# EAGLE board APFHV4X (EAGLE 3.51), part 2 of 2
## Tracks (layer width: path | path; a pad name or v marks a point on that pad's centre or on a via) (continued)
N$22  (via drill 0.05 pad 0.2) (continued)
  Bottom 0.1: v78.55,13.2 v83.92,18.58
N$23  (via drill 0.05 pad 0.2)
  Top 0.2: 85,17.27 85.6,17.27
  Top 0.4: 77.95,11.8 v78.35,11.8
  Top 0.5: v84.72,17.27 85,17.27
  Bottom 0.2: v78.35,11.8 79.25,11.8
  Bottom 0.5: 84.3,16.85 v84.72,17.27
  Bottom 0.8: 79.25,11.8 79.35,11.9
  Bottom 1: 79.35,11.9 84.3,16.85
N$24
  Top 0.4: 77.95,12.3 78.4,12.3 79.32,13.23 79.32,13.43
  Top 0.5: 85.6,17.93 83.82,17.93 83.15,17.25
  Top 1: 79.32,13.43 83.15,17.25
N$25  (via drill 0.05 pad 0.2)
  Top 0.3: v84.75,15.98 85.6,15.98
  Top 0.4: 77.95,10.8 v78.35,10.8
  Bottom 0.2: v78.35,10.8 79.85,10.8
  Bottom 0.3: 84.35,15.3 84.75,15.7 v84.75,15.98
  Bottom 1: 79.85,10.8 84.35,15.3
N$26
  Top 0.1: 85.6,4.28 84.7,4.28 83.7,3.28 77.95,3.28
N$27
  Top 0.1: 85.6,3.63 84.7,3.63 84.05,2.98 77.95,2.98
N$28
  Top 0.1: 85.6,2.98 84.7,2.98 84.4,2.68 JP2_.2
N$29
  Top 0.1: JP2_.6 84.38,2.08 84.78,1.68 85.6,1.68
N$30
  Top 0.1: JP2_.8 84.12,1.78 84.85,1.05 85.22,1.05 85.25,1.03 85.6,1.03
N$32
  Top 0.1: 85.6,2.33 84.67,2.33 84.62,2.38 JP2_.4
N$33
  Top 0.1: JP2_.0 83.75,1.48 84.85,0.38 CN_T.
N$38
  Top 0.075: 13.4,0.8 13.4,0.4
N$39
  Top 0.075: 13.4,1.4 13.4,1
N$40
  Top 0.075: 13.9,0.9 13.5,0.9
N$41
  Top 0.075: 12.9,0.9 13.3,0.9
N$42
  Top 0.075: 13.9,18.7 13.5,18.7
N$43
  Top 0.075: 13.4,18.2 13.4,18.6
N$44
  Top 0.075: 12.9,18.7 13.3,18.7
N$45
  Top 0.075: 13.4,19.2 13.4,18.8
N$46
  Top 0.075: 73.2,18.2 73.2,18.6
N$47
  Top 0.075: 73.7,18.7 73.3,18.7
N$48
  Top 0.075: 72.7,18.7 73.1,18.7
N$49
  Top 0.075: 73.2,19.2 73.2,18.8
N$50
  Top 0.075: 73.2,1.23 73.2,1
N$51
  Top 0.075: 73.2,0.4 73.2,0.8
N$52
  Top 0.075: 73.7,0.9 73.3,0.9
N$53
  Top 0.075: 72.7,0.9 73.1,0.9
NTC
  Top 0.1: 63.35,7.8 63.35,7.15 63.72,6.78 65.45,6.78 65.72,6.5 TR1.
  Top 0.3: 63.35,7.8 63.35,8.62
NTC_RET
  Top 0.1: 61.85,7.8 61.85,7.35 63.67,5.53 64.17,5.53
  Top 0.3: 61.85,7.8 61.85,8.62
RSIB  (via drill 0.05 pad 0.2)
  Top 0.1: 73.3,10.3 72.55,10.3 72.38,10.12 v72.38,9.08 | v35.32,10.5 35.32,6.75 35.55,6.53 U1.B
  Top 0.3: 60.35,7.8 v60.35,8.88 v60.35,10.78
  Bottom 0.1: v60.35,8.88 60.4,8.83 72.12,8.83 v72.38,9.08 | v35.32,10.5 37.45,10.5 38.05,9.9 38.67,9.9 39.02,9.55 40.17,9.55 40.92,10.3 46.52,10.3 47,10.78 v60.35,10.78
STRN  (via drill 0.05 pad 0.2)
  Top 0.075: 15.07,16.93 15.57,17.43 FE-7.2 | 22.67,16.93 23.17,17.43 FE-6.2 | 30.27,16.93 30.77,17.43 FE-5.2 | 37.88,16.93 38.38,17.43 FE-4.2 | 45.47,16.93 45.97,17.43 FE-3.2 | 53.07,16.93 53.57,17.43 FE-2.2 | 60.67,16.93 61.17,17.43 FE-1.2 | 68.28,16.93 68.78,17.43 FE-0.2 | 18.32,2.68 17.82,2.18 FE-8.2 | 25.92,2.68 25.42,2.18 FE-9.2 | 33.52,2.68 33.02,2.18 FE-10.2 | 41.12,2.68 40.62,2.18 FE-11.2 | 56.32,2.68 55.82,2.18 FE-13.2 | 63.92,2.68 63.42,2.18 FE-14.2 | 71.53,2.68 71.03,2.18 FE-15.2 | 48.72,2.68 48.22,2.18 FE-12.2
  Top 0.1: v15.07,15.7 15.07,16.93 | v22.67,15.7 22.67,16.93 | v30.25,15.7 30.27,15.7 30.27,16.93 | v37.88,15.7 37.88,16.93 | v45.47,15.7 45.47,16.93 | v53.07,15.7 53.07,16.93 | v60.67,15.7 60.67,16.93 | v68.28,15.7 68.28,16.93 | 18.32,2.68 18.32,3.35 v18.87,3.9 | v25.92,3.9 25.92,2.68 | v33.52,3.9 33.52,2.68 | v41.12,3.9 41.12,2.68 | v56.32,3.9 56.32,2.68 | v63.92,3.9 63.92,2.68 | 71.53,2.68 v71.53,3.9 71.9,3.9 72.82,2.98 73.3,2.98 | v48.72,3.9 48.72,2.68 | U1.ON 29.02,7.88 v29.02,7.93 29.02,9.6 28.8,9.83 v28.8,15.7 | v30.37,3.85 30.05,4.18 v30.05,7.93 | v30.37,3.85 30.32,3.8 | 29.2,3.38 29.9,3.38 v30.37,3.85
  Bottom 0.1: v71.53,3.9 v63.92,3.9 v56.32,3.9 v48.72,3.9 v41.12,3.9 41.12,3.88 41.05,3.8 34,3.8 33.9,3.9 v33.52,3.9 30.37,3.9 | v18.87,3.9 v25.92,3.9 26.3,3.9 26.4,3.8 30.12,3.8 30.22,3.9 30.37,3.9 | v15.07,15.7 v22.67,15.7 v28.8,15.7 v30.25,15.7 v37.88,15.7 v45.47,15.7 v53.07,15.7 v60.67,15.7 v68.28,15.7 | v30.05,7.93 v29.02,7.93 | 30.37,3.9 v30.37,3.85
STRP  (via drill 0.05 pad 0.2)
  Top 0.075: 14.82,17.02 15.42,17.62 FE-7.3 | 22.42,17.02 23.02,17.62 FE-6.3 | 30.05,17.05 30.62,17.62 FE-5.3 | 37.62,17.02 38.22,17.62 FE-4.3 | 52.82,17.02 53.42,17.62 FE-2.3 | 60.42,17.02 61.02,17.62 FE-1.3 | 68.03,17.02 68.62,17.62 FE-0.3 | 18.55,2.55 17.97,1.98 FE-8.3 | 26.17,2.58 25.57,1.98 FE-9.3 | 33.75,2.55 33.17,1.98 FE-10.3 | 41.38,2.58 40.77,1.98 FE-11.3 | 56.55,2.55 55.97,1.98 FE-13.3 | 64.15,2.55 63.57,1.98 FE-14.3 | 71.75,2.55 71.17,1.98 FE-15.3 | 48.95,2.55 48.38,1.98 FE-12.3 | FE-3.3 45.82,17.6 45.22,17
  Top 0.1: v14.82,15.95 14.82,17.02 | v22.42,15.95 22.42,17.02 | v37.62,15.95 37.62,17.02 | v45.22,15.95 45.22,17 | v52.82,15.95 52.82,17.02 | v60.42,15.95 60.42,17.02 | v68.03,15.95 68.03,17.02 | 18.55,2.55 18.55,2.98 v19.22,3.65 | 26.17,2.58 v26.17,3.65 26.87,3.65 | v41.38,3.65 41.38,2.58 | 56.55,2.55 56.57,2.58 v56.57,3.65 | 64.15,2.55 64.17,2.58 v64.17,3.65 | 71.75,2.55 71.78,2.58 71.78,3.13 | v71.78,3.65 71.78,3.13 | JP2_.1 72.72,2.68 72.28,3.13 71.78,3.13 | 48.95,2.55 48.97,2.58 v48.97,3.65 | v27.95,7.73 U1.OP | v26.92,15.95 v26.92,7.73 26.87,7.68 26.87,3.65 | R13. 27.15,3.38 26.87,3.65 | 30.05,17.05 30.02,17.02 v30.02,15.95 | v33.77,3.65 33.77,3.6 33.77,2.58 33.75,2.55
  Bottom 0.1: v71.78,3.65 v64.17,3.65 v56.57,3.65 v48.97,3.65 v41.38,3.65 41.32,3.6 33.82,3.6 v33.77,3.65 33.77,3.6 26.22,3.6 v26.17,3.65 v19.22,3.65 | v14.82,15.95 v22.42,15.95 v26.92,15.95 v30.02,15.95 v37.62,15.95 v45.22,15.95 v52.82,15.95 v60.42,15.95 v68.03,15.95 | v26.92,7.73 v27.95,7.73
SYNCN  (via drill 0.05 pad 0.2)
  Top 0.075: 16.57,16.75 16.47,16.85 16.47,18.05 | 24.17,16.75 24.07,16.85 24.07,18.05 | 31.77,16.75 31.67,16.85 31.67,18.05 | 39.38,16.75 39.27,16.85 39.27,18.05 | 46.97,16.75 46.88,16.85 46.88,18.05 | 54.57,16.75 54.47,16.85 54.47,18.05 | 62.17,16.75 62.07,16.85 62.07,18.05 | 69.78,16.75 69.67,16.85 69.67,18.05 | 16.82,2.85 16.92,2.75 16.92,1.55 | 24.42,2.85 24.52,2.75 24.52,1.55 | 32.02,2.85 32.12,2.75 32.12,1.55 | 39.62,2.85 39.72,2.75 39.72,1.55 | 62.42,2.85 62.52,2.75 62.52,1.55 | 47.22,2.85 47.32,2.75 47.32,1.55 | 54.82,2.85 54.92,2.75 54.92,1.55 | 70.03,2.85 70.12,2.75 70.12,1.55
  Top 0.1: v16.57,14.2 16.57,16.75 | v24.17,14.2 24.17,16.75 | v31.77,14.2 31.77,16.75 | v39.38,14.2 39.38,16.75 | v46.97,14.2 46.97,16.75 | v54.57,14.2 54.57,16.75 | v62.17,14.2 62.17,16.75 | v69.78,14.2 69.78,16.75 | v16.82,4.28 16.82,2.85 | v24.42,5.4 24.42,2.85 | v39.62,5.4 39.62,2.85 | v54.82,5.4 54.82,2.85 | v62.42,5.4 62.42,2.85 | 70.03,2.85 v70.03,5.4 71.95,5.4 72.57,4.78 73.3,4.78 | v47.22,5.4 47.22,2.85 | v32.02,5.4 32.02,2.85 | v28.65,6.68 U1.CN | v29.47,5.4 v29.47,6.68 | v29.3,14.2 29.3,9.95 29.52,9.73 v29.52,8.98 29.8,8.7 v29.8,7.35 | 25.47,9.62 25.47,9.12 v25.62,8.98
  Bottom 0.075: 27.02,5 26.62,5.4
  Bottom 0.1: v16.57,14.2 v24.17,14.2 v29.3,14.2 v31.77,14.2 v39.38,14.2 v46.97,14.2 v54.57,14.2 v62.17,14.2 v69.78,14.2 | v70.03,5.4 v62.42,5.4 v54.82,5.4 v47.22,5.4 v39.62,5.4 39.62,5.38 39.25,5 34.62,5 34.22,5.4 v32.02,5.4 v29.47,5.4 29.32,5.4 28.92,5 27.02,5 | 26.62,5.4 v24.42,5.4 17.05,5.4 16.82,5.18 v16.82,4.28 | v29.47,6.68 v28.65,6.68 | v29.52,8.98 v25.62,8.98 | v29.47,6.68 29.47,6.65 | v29.8,7.35 29.47,7.03 v29.47,6.68
SYNCP  (via drill 0.05 pad 0.2)
  Top 0.075: 16.32,16.45 16.32,18.05 | 23.92,16.45 23.92,18.05 | 31.52,16.45 31.52,18.05 | 39.12,16.45 39.12,18.05 | 46.72,16.45 46.72,18.05 | 54.32,16.45 54.32,18.05 | 61.92,16.45 61.92,18.05 | 69.53,16.45 69.53,18.05 | 17.07,3.15 17.07,1.55 | 24.67,3.15 24.67,1.55 | 32.27,3.15 32.27,1.55 | 39.88,3.15 39.88,1.55 | 47.47,3.15 47.47,1.55 | 55.07,3.15 55.07,1.55 | 62.67,3.15 62.67,1.55 | 70.28,3.15 70.28,1.55 | 26.62,6.5 v26.62,6.53 | v26.62,14.45 26.62,14.48
  Top 0.1: v16.32,14.45 16.32,16.45 | v23.92,14.45 23.92,16.45 | v31.52,14.45 31.52,16.45 | v39.12,14.45 39.12,16.45 | v46.72,14.45 46.72,16.45 | v54.32,14.45 54.32,16.45 | v61.92,14.45 61.92,16.45 | v69.53,14.45 69.53,16.45 | v17.07,4.08 17.07,3.15 | v24.67,5.15 24.67,3.15 | v32.27,5.15 32.27,3.15 | v39.88,5.15 39.88,3.15 | v55.07,5.15 55.07,3.15 | v62.67,5.15 62.67,3.15 | v70.28,5.15 70.28,3.15 | v72.95,4.48 JP2_. | v47.47,5.15 47.47,3.15 | v27.95,6.53 U1.CP | v26.62,6.53 26.62,10.35 | 26.62,10.35 v26.62,14.45 | R10. 24.37,10.2 v24.52,10.35 | 26.62,10.35 v26.67,10.35 | 26.62,6.5 26.62,5.38 v26.4,5.15
  Bottom 0.1: v16.32,14.45 v23.92,14.45 v26.62,14.45 v31.52,14.45 v39.12,14.45 v46.72,14.45 v54.32,14.45 v61.92,14.45 v69.53,14.45 | v17.07,4.08 17.07,4.83 17.4,5.15 v24.67,5.15 v26.4,5.15 26.57,5.15 26.92,4.8 29.12,4.8 29.47,5.15 v32.27,5.15 34.15,5.15 34.5,4.8 39.55,4.8 39.88,5.13 v39.88,5.15 v47.47,5.15 v55.07,5.15 v62.67,5.15 v70.28,5.15 70.88,5.15 71.55,4.48 v72.95,4.48 | v26.62,6.53 v27.95,6.53 | v26.67,10.35 v24.52,10.35
TS1
  Top 1: 1.5,18.27 1.5,8.28
TS2
  Top 0.1: 2.62,12.23 2.62,2.23
TS3  (via drill 0.05 pad 0.2)
  Top 0.1: v5.9,12.68 5.9,13.15 | v5.9,3.75 5.9,3.15
  Bottom 0.1: v5.9,12.68 v5.9,3.75
TS-VIA1  (via drill 0.05 pad 0.2)
  Top 0.1: v3.6,16.2 3.6,16 3.9,16 v3.9,16.2 | v3.6,16.5 3.6,16.7 | v3.9,16.5 3.9,16.7 4.2,16.7 v4.2,16.5 | v4.2,16.2 4.2,16 4.5,16 v4.5,16.2 | v4.5,16.5 4.5,16.7 4.8,16.7 v4.8,16.5 | v4.8,16.2 4.8,16 5.1,16 v5.1,16.2 | v5.1,16.5 5.1,16.7 5.4,16.7 v5.4,16.5 | v5.4,16.2 5.4,16 5.7,16 v5.7,16.2 | v5.7,16.5 5.7,16.7 6,16.7 v6,16.5 | v6,16.2 6,16 6.3,16 v6.3,16.2 | v6.3,16.5 6.3,16.7 6.6,16.7 v6.6,16.5 | v6.6,16.2 6.6,16 6.9,16 v6.9,16.2 | v6.9,16.5 6.9,16.7 7.2,16.7 v7.2,16.5 | v7.2,16.2 7.2,16 7.5,16 v7.5,16.2 | v7.5,16.5 7.5,16.7 7.8,16.7 v7.8,16.5 | v7.8,16.2 7.8,16 8.1,16 v8.1,16.2 | v8.1,16.5 8.1,16.7
  Bottom 0.1: v3.6,16.2 v3.6,16.5 | v3.9,16.5 v3.9,16.2 | v4.2,16.2 v4.2,16.5 | v4.5,16.5 v4.5,16.2 | v4.8,16.2 v4.8,16.5 | v5.1,16.5 v5.1,16.2 | v5.4,16.2 v5.4,16.5 | v5.7,16.5 v5.7,16.2 | v6,16.2 v6,16.5 | v6.3,16.5 v6.3,16.2 | v6.6,16.2 v6.6,16.5 | v6.9,16.5 v6.9,16.2 | v7.2,16.2 v7.2,16.5 | v7.5,16.5 v7.5,16.2 | v7.8,16.2 v7.8,16.5 | v8.1,16.5 v8.1,16.2
TS-VIA2  (via drill 0.05 pad 0.2)
  Top 0.1: v3.6,15.08 3.6,14.88 3.9,14.88 v3.9,15.08 | v3.6,15.38 3.6,15.58 | v3.9,15.38 3.9,15.58 4.2,15.58 v4.2,15.38 | v4.2,15.08 4.2,14.88 4.5,14.88 v4.5,15.08 | v4.5,15.38 4.5,15.58 4.8,15.58 v4.8,15.38 | v4.8,15.08 4.8,14.88 5.1,14.88 v5.1,15.08 | v5.1,15.38 5.1,15.58 5.4,15.58 v5.4,15.38 | v5.4,15.08 5.4,14.88 5.7,14.88 v5.7,15.08 | v5.7,15.38 5.7,15.58 6,15.58 v6,15.38 | v6,15.08 6,14.88 6.3,14.88 v6.3,15.08 | v6.3,15.38 6.3,15.58 6.6,15.58 v6.6,15.38 | v6.6,15.08 6.6,14.88 6.9,14.88 v6.9,15.08 | v6.9,15.38 6.9,15.58 7.2,15.58 v7.2,15.38 | v7.2,15.08 7.2,14.88 7.5,14.88 v7.5,15.08 | v7.5,15.38 7.5,15.58 7.8,15.58 v7.8,15.38 | v7.8,15.08 7.8,14.88 8.1,14.88 v8.1,15.08 | v8.1,15.38 8.1,15.58
  Bottom 0.1: v3.6,15.08 v3.6,15.38 | v3.9,15.38 v3.9,15.08 | v4.2,15.08 v4.2,15.38 | v4.5,15.38 v4.5,15.08 | v4.8,15.08 v4.8,15.38 | v5.1,15.38 v5.1,15.08 | v5.4,15.08 v5.4,15.38 | v5.7,15.38 v5.7,15.08 | v6,15.08 v6,15.38 | v6.3,15.38 v6.3,15.08 | v6.6,15.08 v6.6,15.38 | v6.9,15.38 v6.9,15.08 | v7.2,15.08 v7.2,15.38 | v7.5,15.38 v7.5,15.08 | v7.8,15.08 v7.8,15.38 | v8.1,15.38 v8.1,15.08
TS-VIA-3
  Top 0.1: 3.62,14.45 3.62,13.75 3.92,13.75 3.92,14.45 4.22,14.45 4.22,13.75 4.52,13.75 4.52,14.45 4.82,14.45 4.82,13.75 5.12,13.75 5.12,14.45 5.42,14.45 5.42,13.75 5.72,13.75 5.72,14.45 6.02,14.45 6.02,13.75 6.32,13.75 6.32,14.45 6.62,14.45 6.62,13.75 6.92,13.75 6.92,14.45 7.22,14.45 7.22,13.75 7.52,13.75 7.52,14.45 7.82,14.45 7.82,13.75 8.12,13.75 8.12,14.45
VCAL  (via drill 0.05 pad 0.2)
  Top 0.075: 17.37,19.4 17.37,18.05
  Top 0.1: 73.3,13.3 72.82,13.3 v72.82,14.12 72.82,17.3 72.5,17.62 72.5,19.4 70.57,19.4 | 54.02,0.3 61.62,0.3 | 54.02,0.3 46.42,0.3 | 46.42,0.3 38.82,0.3 | 38.82,0.3 31.22,0.3 | 31.22,0.3 23.62,0.3 | 23.62,0.3 16.02,0.3 16.02,1.55 | 70.57,19.4 62.97,19.4 | 62.97,19.4 55.38,19.4 | 55.38,19.4 47.77,19.4 | 47.77,19.4 40.17,19.4 | 40.17,19.4 32.57,19.4 | 32.57,19.4 24.97,19.4 | 24.97,19.4 17.37,19.4 | 61.62,0.3 69.22,0.3 | 69.22,0.3 v72.45,0.3 | v53.85,7.45 53.85,7.8 | 54.02,1.55 54.02,0.3 | 55.38,19.4 55.38,18.05 | 62.97,19.4 62.97,18.05 | 70.57,19.4 70.57,18.05 | 47.77,19.4 47.77,18.05 | 40.17,19.4 40.17,18.05 | 32.57,19.4 32.57,18.05 | 24.97,19.4 24.97,18.05 | 23.62,0.3 23.62,1.55 | 31.22,0.3 31.22,1.55 | 38.82,0.3 38.82,1.55 | 46.42,0.3 46.42,1.55 | 61.62,0.3 61.62,1.55 | 69.22,0.3 69.22,1.55
  Bottom 0.1: v53.85,7.45 54.1,7.2 60.8,7.2 60.9,7.3 61.32,7.3 61.42,7.2 63.5,7.2 63.85,6.85 66.9,6.85 66.97,6.93 71.53,6.93 72.45,6 73.9,6 73.9,5.93 | v72.45,0.3 73.38,0.3 73.9,0.83 73.9,5.93 | 73.9,5.93 73.9,13.85 73.62,14.12 v72.82,14.12
VDD  (via drill 0.05 pad 0.2)
  Top 0.1: v71.32,18.4 71.32,18.05 | v68.47,18.35 FE-0.4 | v63.72,18.5 63.72,18.05 | v40.92,18.5 40.92,18.05 | v45.67,18.45 FE-3.4 | v60.88,18.5 FE-1.4 | v56.12,18.5 56.12,18.05 | v53.27,18.5 FE-2.4 | v48.52,18.5 48.52,18.05 | v38.07,18.5 FE-4.4 | v33.32,18.5 33.32,18.05 | v30.47,18.5 FE-5.4 | v25.72,18.5 25.72,18.05 | v22.87,18.5 FE-6.4 | v18.12,18.5 18.12,18.05 | v15.27,18.5 FE-7.4 | v15.27,1.1 15.27,1.55 | v18.12,1.1 FE-8.4 | v22.87,1.1 22.87,1.55 | v25.72,1.12 FE-9.4 | v30.47,1.1 30.47,1.55 | v33.32,1.1 FE-10.4 | v38.07,1.1 38.07,1.55 | v45.67,1.1 45.67,1.55 | v40.92,1.1 FE-11.4 | v48.52,1.1 FE-12.4 | 53.27,1.55 v53.27,1.12 | v56.12,1.1 FE-13.4 | v60.88,1.1 60.88,1.55 | v63.72,1.1 FE-14.4 | v68.47,1.1 68.47,1.55 | v71.32,1.1 FE-15.4 | v72.92,1.78 JP2_.7 | 33.4,10.1 33.4,9.75 33.35,9.7 33.35,9.48 | 36.7,7.43 36.17,7.43 36.07,7.53 v36.07,8.48 36.7,8.48 | 36.7,6.08 37.45,6.08 37.52,6 | 27.77,8.33 28.3,8.33 | v28.3,5.93 28.3,6.08 27.75,6.08 | 36.52,8.78 C5. | 36.7,8.48 36.72,8.48 | 27.67,7.43 28.3,7.43 | 36.52,8.58 36.62,8.48 36.7,8.48
  Top 0.2: 57.35,7.2 56.97,6.83 | 27.35,8.33 27.77,8.33 27.42,8.33 | 27.4,7.28 27.55,7.43 27.67,7.43 27.42,7.43
  Top 0.3: v61.92,11.18 61.92,11.4 61.7,11.62 59.45,11.62 58.9,11.08 v58.9,9.95 | 33.35,9.48 v33.35,8.15 33.35,7.13 33.07,6.85 | 37.52,6 37.52,5.28 37.42,5.18 34,5.18 | 36.52,8.58 36.52,8.78
  Top 0.4: v71.28,11.8 73.3,11.8 | 34,5.18 33.95,5.18 33.07,6.05 v33.07,6.4
  Top 0.5: v57.35,8.9 57.35,7.83 | 57.35,7.83 57.35,7.8 | 65.32,18.83 66.1,18.83 v66.1,18.23 | 42.5,18.83 43.3,18.83 v43.3,18.23 43.3,16.25 43.42,16.25 | 57.72,18.83 58.4,18.83 58.5,18.73 v58.5,18.23 | 50.12,18.83 50.9,18.83 v50.9,18.23 | 34.92,18.83 35.7,18.83 v35.7,18.23 | 27.32,18.83 28.1,18.83 v28.1,18.23 | 19.72,18.83 20.5,18.83 v20.5,18.23 | 21.3,1 20.5,1 v20.5,1.38 | 28.87,1 28.12,1 v28.12,1.38 | 36.47,1 35.72,1 v35.72,1.38 35.72,3.83 C1. 35.57,4.88 35.27,5.18 34,5.18 | 43.05,3.33 43.07,3.33 43.3,3.33 v43.3,1.38 43.3,1 44.07,1 | 51.67,1 50.9,1 v50.9,1.38 | 59.27,1 58.5,1 v58.5,1.38 | 66.88,1 66.1,1 v66.1,1.38 | 43.42,9.55 43.07,9.55 C21. | 43.07,8 v43.07,8.9 | v43.07,8.9 C21. | v43.07,8.9 C21. | 57.35,7.83 57.35,7.2 | 56.97,6.83 C2. | v33.07,6.4 33.07,6.85 | 27.4,6.43 27.4,7.28 | 27.42,7.43 27.42,8.33 | 27.75,6.08 27.4,6.43 | C22. 27.4,4.6 27.4,6.43
  Top 1: 43.42,9.55 43.42,16.25 | 43.07,3.33 43.07,8
  Bottom 0: v71.32,18.4 71.32,18.23 72.03,18.23 | 63.72,18.23 v63.72,18.5 | 40.92,18.23 v40.92,18.5 | 45.67,18.23 v45.67,18.45 | 60.88,18.23 v60.88,18.5 | 56.12,18.23 v56.12,18.5 | 53.27,18.23 v53.27,18.5 | 48.52,18.23 v48.52,18.5 | 38.07,18.23 v38.07,18.5 | 33.32,18.23 v33.32,18.5 | 30.47,18.23 v30.47,18.5 | 25.72,18.23 v25.72,18.5 | 22.87,18.23 v22.87,18.5 | 18.12,18.23 v18.12,18.5 | 15.27,18.23 v15.27,18.5 | 15.27,1.38 v15.27,1.1 | 18.12,1.38 v18.12,1.1 | 22.87,1.38 v22.87,1.1 | 25.72,1.38 v25.72,1.12 | 30.47,1.38 v30.47,1.1 | 33.32,1.38 v33.32,1.1 | 38.07,1.38 v38.07,1.1 | 45.67,1.38 v45.67,1.1 | 40.92,1.38 v40.92,1.1 | 48.52,1.38 v48.52,1.1 | v53.27,1.12 53.27,1.38 | 56.12,1.38 v56.12,1.1 | 60.88,1.38 v60.88,1.1 | 63.72,1.38 v63.72,1.1 | 68.47,1.38 v68.47,1.1 | 71.32,1.38 v71.32,1.1
  Bottom 0.1: 68.47,18.23 v68.47,18.35 | 72,1.38 72.53,1.38 v72.92,1.78 | v33.07,6.4 28.77,6.4 v28.3,5.93
  Bottom 0.2: v36.07,8.48 36.07,8.38 35.88,8.38 35.88,8.15
  Bottom 0.3: v71.28,11.8 70.5,11.8 69.88,11.18 v61.92,11.18 | v58.9,9.95 58.4,9.95 v57.35,8.9
  Bottom 0.5: 57.1,9.15 57.35,9.15 v57.35,8.9 | 48.52,9.15 48.52,8.9 v43.07,8.9 | v33.35,8.15 35.88,8.15
  Bottom 0.75: 14.37,18.23 15.27,18.23 18.12,18.23 v20.5,18.23 22.87,18.23 25.72,18.23 v28.1,18.23 30.47,18.23 33.32,18.23 v35.7,18.23 38.07,18.23 40.92,18.23 v43.3,18.23 45.67,18.23 48.52,18.23 v50.9,18.23 53.27,18.23 56.12,18.23 v58.5,18.23 60.88,18.23 63.72,18.23 v66.1,18.23 68.47,18.23 72.03,18.23 72.07,18.23 | 72,1.38 71.32,1.38 68.47,1.38 v66.1,1.38 63.72,1.38 60.88,1.38 v58.5,1.38 56.12,1.38 53.27,1.38 v50.9,1.38 48.52,1.38 45.67,1.38 v43.3,1.38 40.92,1.38 38.07,1.38 v35.72,1.38 33.32,1.38 30.47,1.38 v28.12,1.38 25.72,1.38 22.87,1.38 v20.5,1.38 18.12,1.38 15.27,1.38 14.5,1.38
  Bottom 1: 48.52,9.15 57.1,9.15
VDDA  (via drill 0.05 pad 0.2)
  Top 0: 28.87,16.83 28.9,16.8 v28.87,16.8 | v51.67,16.8 51.65,16.83 51.67,16.83 | 67.95,18.05 FE-0.8 | 64.25,18.05 64.32,18.05 | 56.65,18.05 56.72,18.05 | FE-1.8 FE-1.7 | 49.2,17.4 49.05,17.4 | 49.05,18.05 49.12,18.05 | 41.45,18.05 41.38,18.05 | 36.5,17.58 36.5,17.55 36.47,17.52 | 33.77,18.05 33.92,18.05 33.85,18.05 | 33.85,17.35 33.85,17.38 34,17.38 | 29.95,18.05 FE-5.8 | 18.57,18.05 18.72,18.05 18.65,18.05 | 18.8,17.38 18.65,17.38 | 14.67,1.55 14.75,1.55 14.82,1.55 | 22.1,2.23 22.27,2.23 | 30.02,1.55 29.87,1.55 29.95,1.55 | 37.62,1.55 37.47,1.55 37.55,1.55 | 37.4,2.23 37.55,2.23 | 45.15,1.58 45.07,1.55 | 52.82,1.55 52.75,1.55 52.67,1.55 | 52.75,2.23 52.6,2.23 | 60.42,1.55 60.35,1.55 60.27,1.55 | 60.2,2.23 60.35,2.23 | 26.17,18.05 26.32,18.05 26.25,18.05 | 26.4,17.38 26.25,17.38 | 22.3,1.55 22.32,1.58 22.27,1.55 22.3,1.55
  Top 0.075: 26.52,2.1 26.32,1.9 FE-9.8 | 34.12,2.1 33.92,1.9 FE-10.8 | 49.32,2.1 49.12,1.9 FE-12.8 | 56.92,2.1 56.72,1.9 FE-13.8 | 64.53,2.1 64.32,1.9 FE-14.8 | v42.52,2.8 42.52,2.1 42.35,1.93 | 41.65,1.93 41.52,1.8 FE-11.8 | 67.88,2.1 67.88,1.55
  Top 0.1: 51.67,17.52 52.5,17.52 52.67,17.7 FE-2.8 FE-2.7 | 21.27,17.52 22.1,17.52 22.27,17.7 FE-6.8 FE-6.7 | 18.92,2.1 18.72,1.9 FE-8.8 FE-8.7 | JP2_.3 73.1,2.38 73,2.48 72.17,2.48 | 44.1,17.73 44.12,17.7 44.15,17.7 44.2,17.65 44.95,17.65 45.07,17.77 FE-3.8 FE-3.7 | 42.35,1.93 41.65,1.93 | 14.42,17.45 14.67,17.7 FE-7.8 FE-7.7 | 71.92,1.95 FE-15.8 FE-15.7 | FE-1.8 60.35,18.05 60.35,17.7 60.27,17.62 59.27,17.62 | 71.78,18.05 71.92,18.05 71.85,18.05 | FE-0.7 67.95,18.05 67.95,17.75 67.8,17.6 66.88,17.6 | 64.32,18.05 64.17,18.05 | 64.4,17.38 64.25,17.38 | 56.72,18.05 56.57,18.05 | 49.12,18.05 48.97,18.05 | 41.52,18.05 41.45,18.05 41.45,17.48 41.25,17.27 | 37.55,18.05 FE-4.8 | 37.55,18.05 FE-4.7 | 37.55,18.05 37.55,17.7 37.42,17.58 36.5,17.58 | FE-5.8 FE-5.7 | 29.95,18.05 29.95,17.7 29.87,17.62 28.87,17.62 | 22.42,1.55 22.27,1.55 22.27,2.23 | FE-9.8 FE-9.7 | FE-10.8 FE-10.7 | FE-11.8 FE-11.7 | 45.07,1.55 45.22,1.55 | FE-12.8 FE-12.7 | FE-13.8 FE-13.7 | FE-14.8 FE-14.7 | 67.88,1.55 68.03,1.55
  Top 0.2: 19.72,2.1 18.92,2.1 | 27.32,2.1 26.52,2.1 | 34.92,2.1 34.12,2.1 | 50.12,2.1 49.32,2.1 | 57.72,2.1 56.92,2.1 | 65.32,2.1 64.53,2.1 | 71.92,1.95 72.17,2.2 72.17,2.48 v72.17,2.8 | v14.42,16.8 14.42,17.45 | v71.85,16.8 71.85,18.05 | 64.25,17.38 64.25,18.05 | 56.8,17.38 56.65,17.38 56.65,18.05 | 49.05,17.4 49.05,18.05 | 33.85,17.38 33.85,18.05 | 18.65,17.38 18.65,18.05 | 29.95,2.23 29.95,2.2 29.95,1.55 | 37.55,2.23 37.55,1.55 | 45.15,2.1 45.15,1.58 | 52.75,1.55 52.75,2.23 | 60.35,2.23 60.35,1.55 | 26.25,17.38 26.25,18.05
  Top 0.25: v14.75,2.8 14.75,1.55 | v45.27,3.08 45.22,3.08 45.15,3
  Top 0.3: v41.25,16.52 41.25,17.27 | 55.35,8.1 55.35,7.8 v55.35,7.5
  Top 0.4: v29.95,2.8 29.95,2.2 | 45.15,3 45.15,2.1 | 73.3,10.8 71.6,10.8 v70.97,10.18
  Top 0.5: v66.88,16.8 66.88,17.6 66.88,17.73 | v64.4,16.8 64.4,17.38 | v59.27,16.8 59.27,17.62 59.27,17.73 | v56.8,16.8 56.8,17.38 | 51.67,16.83 51.67,17.52 51.67,17.73 | v49.2,16.8 49.2,17.4 | v36.47,16.8 36.47,17.52 36.47,17.73 | v34,16.8 34,17.38 | 28.87,16.83 28.87,17.62 28.87,17.73 | v26.4,16.8 26.4,17.38 | v21.27,16.8 21.27,17.52 21.27,17.73 | v18.8,16.8 18.8,17.38 | v19.72,2.8 19.72,2.1 | v22.1,2.8 22.1,2.23 | v27.32,2.8 27.32,2.1 | v34.92,2.8 34.92,2.1 | v37.4,2.8 37.4,2.23 | v50.12,2.8 50.12,2.1 | 52.6,2.23 v52.6,2.8 | v57.72,2.8 57.72,2.1 | v60.2,2.8 60.2,2.23 | v65.32,2.8 65.32,2.1 | v67.88,2.8 67.88,2.1 | v44.52,16.52 44.52,17.5 44.1,17.5 44.1,17.73 | 48.8,8.68 C3. | C6. 45.02,9.15 45.27,9.15 | v20.45,3.08 20.45,4.2
  Top 1: 55.35,8.1 55.35,8.68 48.8,8.68 45.27,8.68 | v45.27,3.08 45.27,8.68 | v44.52,16.52 44.52,9.9 45.27,9.15 45.27,8.68
  Bottom 0: 36.47,3.08 36.47,2.8 | 34.05,3.08 34.3,2.8 | 37.12,16.8 37.12,16.15 | 21.92,16.8 21.92,16.15 | 18.72,16.52 v18.8,16.8 v21.27,16.8 21.92,16.8 | v59.27,16.8 59.92,16.15 | 56.72,16.52 v56.8,16.8 | v56.8,16.8 v59.27,16.8 | 67.53,16.15 v66.88,16.8 v64.4,16.8 | v64.4,16.8 64.32,16.52 | v59.27,16.8 v64.4,16.8 | v56.8,16.8 v59.27,16.8 | v49.2,16.8 52.32,16.8 52.32,16.15 51.67,16.83 | v44.52,16.52 v41.25,16.52 | 37.12,16.8 v34,16.8 | v71.85,16.8 71.92,16.52 71.9,16.52 71.88,16.5 71.85,16.52 71.82,16.52 | 29.52,16.8 29.52,16.15 | v26.4,16.8 26.32,16.52 | 37.12,16.8 29.52,16.8 | v26.4,16.8 v28.87,16.8 29.52,16.8 | v26.4,16.8 21.92,16.8 | v49.2,16.8 49.12,16.52 | v49.2,16.8 v51.67,16.8 | v56.8,16.8 51.67,16.83 | v49.2,16.8 v51.67,16.8 | v51.67,16.8 51.67,16.83 | v44.52,16.52 v49.2,16.8 | v44.52,16.52 v49.2,16.8 | v41.25,16.52 44.22,16.8 v44.52,16.52 | v41.25,16.52 37.12,16.8 | 33.92,16.52 v34,16.8 | v36.47,16.8 v34,16.8 | v41.25,16.52 v36.47,16.8 | v36.47,16.8 v34,16.8 | v34,16.8 29.52,16.8 | 19.07,2.8 19.07,3.45 | 22.27,3.08 v22.1,2.8 | 19.07,2.8 v14.75,2.8 | v22.1,2.8 v19.72,2.8 19.07,2.8 | v22.1,2.8 v27.32,2.8 | 28.45,3.35 29.87,3.08 v29.95,2.8 v34.92,2.8 | 36.05,3.35 37.47,3.08 v37.4,2.8 | 44.07,3.08 44.07,2.8 | 41.65,3.08 41.9,2.8 | 43.65,3.35 v45.27,3.08 v50.12,2.8 | 51.67,3.08 51.67,2.8 | 49.25,3.08 49.5,2.8 | 51.25,3.35 52.67,3.08 v52.6,2.8 v57.72,2.8 | 59.27,3.08 59.27,2.8 | 56.85,3.08 57.1,2.8 | 58.85,3.35 60.27,3.08 v60.2,2.8 v65.32,2.8 | 66.88,3.08 66.88,2.8 | 64.45,3.08 64.7,2.8 | 66.45,3.35 67.88,3.08 v67.88,2.8 | 71.95,3.08 71.95,3.05 v72.17,2.8 72.15,2.83 72.15,2.98 72.05,3.08 | 71.92,3.08 72,3.08
  Bottom 0.075: 52.32,16.8 v56.8,16.8 | v37.4,2.8 v42.52,2.8
  Bottom 0.2: 14.67,16.52 14.65,16.52 14.42,16.75 v14.42,16.8 | 44.22,16.8 43.92,16.8
  Bottom 0.3: v70.97,10.18 66.8,10.18 66.53,9.9 60.42,9.9 59.35,8.83 58.85,8.83 57.52,7.5 v55.35,7.5
  Bottom 0.75: 67.88,3.08 36.47,3.08 34.05,3.08 29.87,3.08 | 26.75,3.08 29.87,3.08 | 26.75,3.08 v20.45,3.08 14.67,3.08 | 33.92,16.52 14.67,16.52 | v44.52,16.52 71.82,16.52 | 33.92,16.52 v41.25,16.52 v44.52,16.52 | v44.52,16.52 56.72,16.52 | 33.92,16.52 18.72,16.52 | 37.47,3.08 41.65,3.08 44.07,3.08 | 37.47,3.08 26.75,3.08 | 26.75,3.08 22.27,3.08 | v45.27,3.08 49.25,3.08 51.67,3.08 | 29.87,3.08 v45.27,3.08 | 52.67,3.08 56.85,3.08 59.27,3.08 | 52.67,3.08 37.47,3.08 | v45.27,3.08 60.27,3.08 64.45,3.08 66.88,3.08 | 67.88,3.08 71.92,3.08 71.95,3.08 72,3.08 72.05,3.08 | 52.67,3.08 67.88,3.08
VDET
  Top 0.1: R7. 19.8,9.68 HV_PT1.
  Top 0.5: HV_PT1. 19.8,9.73
VDET_RET
  Top 0.1: 21.47,7.85 R5.
  Top 0.5: 21.47,9.73 HV_PT2. 21.47,7.85
WB-L  (31 unrouted)
  Top 0.1: 4.88,5.53 3.95,5.53 | 3.95,5.28 4.9,5.28 | 4.9,5.03 3.95,5.03 | 4.88,6.03 3.95,6.03 | 3.95,5.78 4.88,5.78 | 4.88,6.53 3.95,6.53 | 3.95,6.28 4.88,6.28 | 4.88,7.03 3.95,7.03 | 3.95,6.78 4.88,6.78 | 4.88,7.53 3.95,7.53 | 3.95,7.28 4.88,7.28 | 4.88,8.03 3.95,8.03 | 4.88,8.53 3.95,8.53 | 3.95,8.28 4.88,8.28 | 4.88,9.03 3.95,9.03 | 3.95,8.78 4.88,8.78 | 4.88,9.53 3.95,9.53 | 3.95,9.28 4.88,9.28 | 4.88,10.03 3.95,10.03 | 3.95,9.78 4.88,9.78 | 4.88,10.53 3.95,10.53 | 3.95,10.28 4.88,10.28 | 4.88,11.03 3.95,11.03 | 3.95,10.78 4.88,10.78 | 4.88,11.53 3.95,11.53 | 3.95,11.28 4.88,11.28 | 3.95,11.78 4.88,11.78 | 3.95,12.28 4.88,12.28 | 4.88,12.03 3.95,12.03 | 4.88,12.53 3.95,12.53 | 4.88,12.78 3.95,12.78 | 3.95,7.78 4.88,7.78
WB-R  (31 unrouted)
  Top 0.1: 8,12.78 7.05,12.78 | 8,12.28 7.05,12.28 | 8,12.53 7.05,12.53 | 8,12.03 7.05,12.03 | 8,11.78 7.05,11.78 | 8,11.53 7.05,11.53 | 8,11.28 7.05,11.28 | 8,11.03 7.05,11.03 | 8,10.78 7.05,10.78 | 8,10.53 7.05,10.53 | 8,10.28 7.05,10.28 | 8,10.03 7.05,10.03 | 8,9.78 7.05,9.78 | 8,9.53 7.05,9.53 | 8,9.28 7.05,9.28 | 8,9.03 7.05,9.03 | 8,8.78 7.05,8.78 | 8,8.53 7.05,8.53 | 8,8.28 7.05,8.28 | 8,8.03 7.05,8.03 | 8,7.78 7.05,7.78 | 8,7.53 7.05,7.53 | 8,7.28 7.05,7.28 | 8,7.03 7.05,7.03 | 8,6.78 7.05,6.78 | 8,6.53 7.05,6.53 | 8,6.28 7.05,6.28 | 8,6.03 7.05,6.03 | 8,5.78 7.05,5.78 | 8,5.53 7.05,5.53 | 8,5.28 7.05,5.28 | 8,5.03 7.05,5.03
XCKN  (via drill 0.05 pad 0.2)
  Top 0.075: 16.07,16.55 16.17,16.65 16.17,18.05 | 23.67,16.55 23.77,16.65 23.77,18.05 | 31.27,16.55 31.37,16.65 31.37,18.05 | 38.88,16.55 38.97,16.65 38.97,18.05 | 46.47,16.55 46.57,16.65 46.57,18.05 | 54.07,16.55 54.17,16.65 54.17,18.05 | 61.67,16.55 61.77,16.65 61.77,18.05 | 69.28,16.55 69.38,16.65 69.38,18.05 | 17.32,3.05 17.22,2.95 17.22,1.55 | 24.92,3.05 24.82,2.95 24.82,1.55 | 32.52,3.05 32.42,2.95 32.42,1.55 | 40.12,3.05 40.02,2.95 40.02,1.55 | 55.32,3.05 55.22,2.95 55.22,1.55 | 62.92,3.05 62.82,2.95 62.82,1.55 | 70.53,3.05 70.42,2.95 70.42,1.55 | 47.72,3.05 47.62,2.95 47.62,1.55
  Top 0.1: v16.07,14.7 16.07,16.55 | v23.67,14.7 23.67,16.55 | v31.27,14.7 31.27,16.55 | v38.88,14.7 38.88,16.55 | v46.47,14.7 46.47,16.55 | v54.07,14.7 54.07,16.55 | v61.67,14.7 61.67,16.55 | v69.28,14.7 69.28,16.55 | v17.32,3.9 17.32,3.05 | v24.92,4.9 24.92,3.05 | v32.52,4.9 32.52,3.05 | v40.12,4.9 40.12,3.05 | v55.32,4.9 55.32,3.05 | v62.92,4.9 62.92,3.05 | 70.53,3.05 v70.53,4.9 72.12,4.9 72.85,4.18 73.3,4.18 | v47.72,4.9 47.72,3.05 | U1.INN 28.65,6.98 v28.65,7.28 28.3,7.28 | v29.8,4.9 29.8,6.98 29.5,7.28 v29.3,7.28 29.3,8.83 29.27,8.85 29.27,9.68 29.05,9.9 v29.05,14.7 | v24.42,7.28 24.42,6.73
  Bottom 0.1: v70.53,4.9 v62.92,4.9 v55.32,4.9 v47.72,4.9 v40.12,4.9 40.12,4.88 39.85,4.6 34.4,4.6 34.1,4.9 v32.52,4.9 v29.8,4.9 29.6,4.9 29.3,4.6 26.82,4.6 26.52,4.9 v24.92,4.9 17.75,4.9 17.35,4.5 17.35,3.9 v17.32,3.9 | v16.07,14.7 v23.67,14.7 v29.05,14.7 v31.27,14.7 v38.88,14.7 v46.47,14.7 v54.07,14.7 v61.67,14.7 v69.28,14.7 | v29.3,7.28 v28.65,7.28 v24.42,7.28
XCKP  (via drill 0.05 pad 0.2)
  Top 0.075: 15.82,16.62 16.02,16.83 16.02,18.05 | 23.42,16.62 23.62,16.83 23.62,18.05 | 31.02,16.62 31.22,16.83 31.22,18.05 | 38.62,16.62 38.82,16.83 38.82,18.05 | 46.22,16.62 46.42,16.83 46.42,18.05 | 53.82,16.62 54.02,16.83 54.02,18.05 | 61.42,16.62 61.62,16.83 61.62,18.05 | 69.03,16.62 69.22,16.83 69.22,18.05 | 17.57,2.98 17.37,2.78 17.37,1.55 | 25.17,2.98 24.97,2.78 24.97,1.55 | 32.77,2.98 32.57,2.78 32.57,1.55 | 40.38,2.98 40.17,2.78 40.17,1.55 | 55.57,2.98 55.38,2.78 55.38,1.55 | 63.17,2.98 62.97,2.78 62.97,1.55 | 70.78,2.98 70.57,2.78 70.57,1.55 | 47.97,2.98 47.77,2.78 47.77,1.55
  Top 0.1: v15.82,14.95 15.82,16.62 | v23.42,14.95 23.42,16.62 | v31.02,14.95 31.02,16.62 | v38.62,14.95 38.62,16.62 | v46.22,14.95 46.22,16.62 | v53.82,14.95 53.82,16.62 | v61.42,14.95 61.42,16.62 | v69.03,14.95 69.03,16.62 | 17.57,2.98 17.57,3.83 v17.65,3.9 | v25.17,4.65 25.17,2.98 | v40.38,4.65 40.38,2.98 | 55.57,2.98 v55.57,4.65 | v63.17,4.65 63.17,2.98 | 70.78,2.98 v70.78,4.65 72.07,4.65 72.85,3.88 73.3,3.88 | v47.97,4.65 47.97,2.98 | v32.77,4.65 32.77,2.98 | U1.INP v27.95,6.83 27.95,7.13 28.3,7.13 | v26.15,4.65 26.15,5.3 26.37,5.53 v26.37,7.03 v26.37,14.95 | v25.52,7.03 R12.
  Bottom 0.1: v15.82,14.95 v23.42,14.95 v26.37,14.95 v31.02,14.95 v38.62,14.95 v46.22,14.95 v53.82,14.95 v61.42,14.95 v69.03,14.95 | v70.78,4.65 v63.17,4.65 v55.57,4.65 v47.97,4.65 v40.38,4.65 40.38,4.63 40.15,4.4 34.3,4.4 34.05,4.65 v32.77,4.65 29.75,4.65 29.5,4.4 26.72,4.4 26.47,4.65 v26.15,4.65 v25.17,4.65 17.95,4.65 17.65,4.35 v17.65,3.9 | v27.95,6.83 27.75,7.03 v26.37,7.03 v25.52,7.03
(copper drawn outside any net)
  shapes: Bottom area x11, Top circle x38

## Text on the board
Top: 12/01
tNames: TV1 | TV8 | TV9 | TV16 | TS1 | JP1 | TBP | TS3 | JP2 | TS2
Reference: A | B | C | D
tDocu: FE7 | FE0 | FE8 | FE15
